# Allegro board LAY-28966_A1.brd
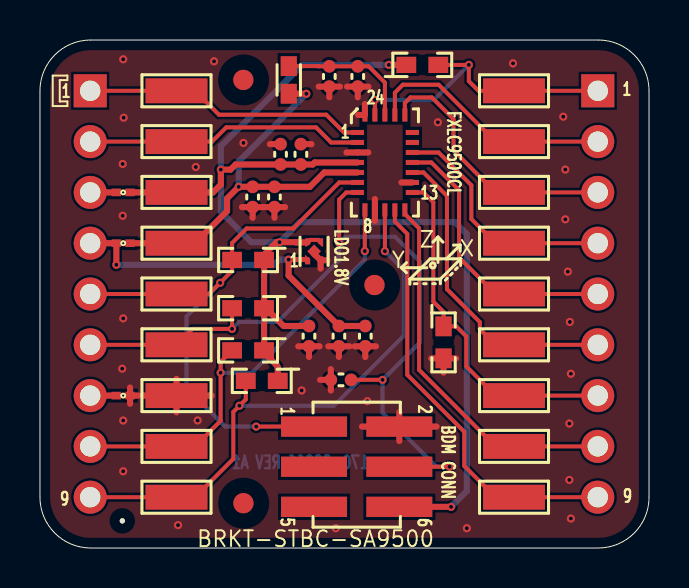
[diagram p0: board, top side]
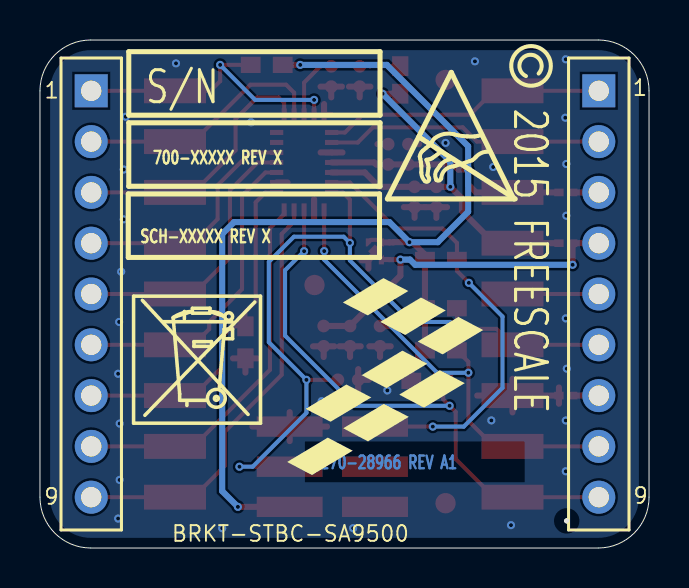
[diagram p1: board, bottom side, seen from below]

Outline 30.48 x 25.4 mm; copper layers: TOP, BOTTOM. Coordinates in mm from the lower left corner of the outline.
Outline path: 0,22.86 0,2.54 arc(0.74,0.74) 2.54,0 27.94,0 arc(29.74,0.74) 30.48,2.54 30.48,22.86 arc(29.74,24.66) 27.94,25.4 2.54,25.4 arc(0.74,24.66) 0,22.86

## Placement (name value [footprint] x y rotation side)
BKG1  0805  [TESTPOINT_122X049MIL]  6.83 12.7 0 top
C1  1uF  [CC0402_25]  10.64 17.55 270 top
C2  0.1uF  [CC0402_25]  11.73 17.55 270 top
C3  1uF  [CC0402_25]  14.48 23.58 270 top
C4  0.1uF  [CC0402_25]  15.9 23.58 270 top
C5  1uF  [CC0402_25]  12.04 19.68 90 top
C6  0.1uF  [CC0402_25]  13.06 19.68 90 top
C7  0.1uF  [CC0402_25]  13.46 10.59 270 top
C8  1uF  [CC0402_25]  16.28 10.59 270 top
C9  0.1uF  [CC0402_25]  14.96 10.59 270 top
C10  22pF  [CC0402_25]  15.06 8.41 180 top
GND1  0805  [TESTPOINT_122X049MIL]  6.83 7.62 0 top
INT0  0805  [TESTPOINT_122X049MIL]  23.72 10.16 0 top
INT1  0805  [TESTPOINT_122X049MIL]  23.72 7.62 0 top
IO6  0805  [TESTPOINT_122X049MIL]  23.72 12.7 0 top
IO7  0805  [TESTPOINT_122X049MIL]  23.72 15.24 0 top
IO12  0805  [TESTPOINT_122X049MIL]  23.72 17.78 0 top
IO13  0805  [TESTPOINT_122X049MIL]  23.72 20.32 0 top
J1  TSW-109-08-G-S  [HDR9_2P54_3X23]  2.51 22.86 180 bottom
J2  TSW-109-08-G-S  [HDR9_2P54_3X23]  27.91 22.86 180 bottom
J3  HDR_2X3  [HDR203_TMM_SM]  15.85 4.06 0 top
L1  600OHM  [IND_0603]  12.45 23.4 270 top
MCL1  0805  [TESTPOINT_122X049MIL]  6.83 22.86 0 top
MDA1  0805  [TESTPOINT_122X049MIL]  6.83 20.32 0 top
NOREF  -  []  5.71 1.92 90 top
NOREF#2  -  []  14.17 14.17 90 top
NOREF#3  -  []  22.72 12.08 90 top
NOREF#4  -  []  22.72 3.17 0 top
NOREF#5  -  []  13.54 18.87 0 top
NOREF#6  -  []  7.83 9.53 90 top
NOREF#7  -  []  5.71 17.16 90 top
NOREF#8  -  []  22.72 9.53 0 top
NOREF#9  -  []  7.83 14.61 90 top
NOREF#10  -  []  5.71 7 90 top
NOREF#11  -  []  22.72 14.62 90 top
NOREF#12  -  []  5.83 4.45 0 top
NOREF#13  -  []  5.83 9.53 0 top
NOREF#14  -  []  22.72 1.92 90 top
NOREF#15  -  []  16.31 19.37 90 top
NOREF#16  -  []  5.71 23.49 0 top
NOREF#17  -  []  4.88 0 90 top
NOREF#18  -  []  22.72 5.71 0 top
NOREF#19  -  []  22.72 7 90 top
NOREF#20  -  []  22.72 1.91 0 top
NOREF#21  -  []  5.71 3.17 0 top
NOREF#22  -  []  24.72 19.69 90 top
NOREF#23  -  []  27.08 0 90 top
NOREF#24  -  []  22.72 9.54 90 top
NOREF#25  -  []  24.72 14.61 90 top
NOREF#26  -  []  5.83 19.69 0 top
NOREF#27  -  []  24.72 12.07 90 top
NOREF#28  -  []  5.71 18.41 0 top
NOREF#29  -  []  16.31 19.37 90 top
NOREF#30  -  []  5.71 13.33 0 top
NOREF#31  -  []  22.72 12.07 0 top
NOREF#32  -  []  22.72 23.49 0 top
NOREF#33  -  []  -12.95 -49.48 0 top
NOREF#34  -  [unnamed#2]  10.18 2.24 180 top
NOREF#35  -  []  7.83 6.99 90 top
NOREF#36  -  []  22.72 4.46 90 top
NOREF#37  -  []  5.83 22.23 0 top
NOREF#38  -  []  22.72 18.41 0 top
NOREF#39  -  []  5.71 9.54 90 top
NOREF#40  -  [unnamed#2]  10.18 23.4 180 top
NOREF#41  -  []  22.72 8.25 0 top
NOREF#42  -  []  5.71 8.25 0 top
NOREF#43  -  []  4.19 1.32 0 top
NOREF#44  -  []  5.71 20.95 0 top
NOREF#45  -  []  5.83 6.99 0 top
NOREF#46  -  []  7.83 22.23 90 top
NOREF#47  -  []  22.72 4.45 0 top
NOREF#48  -  []  22.72 19.7 90 top
NOREF#49  -  []  -310.77 -262.2 0 top
NOREF#50  -  []  22.72 6.99 0 top
NOREF#51  -  []  22.72 19.69 0 top
NOREF#52  -  []  5.71 12.08 90 top
NOREF#53  -  []  22.72 14.61 0 top
NOREF#54  -  []  24.72 9.53 90 top
NOREF#55  -  []  22.72 10.79 0 top
NOREF#56  -  []  7.83 19.69 90 top
NOREF#57  -  []  297.56 -38.68 0 top
NOREF#58  -  []  0 22.65 0 top
NOREF#59  -  []  5.71 22.24 90 top
NOREF#60  -  [unnamed#2]  4.12 1.36 180 top
NOREF#61  -  []  15.54 19.1 90 top
NOREF#62  -  []  22.72 13.33 0 top
NOREF#63  -  []  5.71 5.71 0 top
NOREF#64  -  []  7.83 12.07 90 top
NOREF#65  -  []  5.83 1.91 0 top
NOREF#66  -  []  5.71 4.46 90 top
NOREF#67  -  []  16.31 19.37 90 top
NOREF#68  -  []  22.72 15.87 0 top
NOREF#69  -  [unnamed#2]  16.74 13.15 180 top
NOREF#70  -  []  13.76 19.37 0 top
NOREF#71  -  []  14.54 19.1 0 top
NOREF#72  -  []  7.83 17.15 90 top
NOREF#73  -  []  24.72 17.15 90 top
NOREF#74  -  []  -284.73 262.94 0 top
NOREF#75  -  []  22.72 22.24 90 top
NOREF#76  -  []  25.15 2.97 0 top
NOREF#77  -  []  5.71 19.7 90 top
NOREF#78  -  []  7.83 1.91 90 top
NOREF#79  -  []  7.83 4.45 90 top
NOREF#80  -  []  16.54 18.87 90 top
NOREF#81  -  []  5.83 14.61 0 top
NOREF#82  -  []  0 4.18 0 top
NOREF#83  -  []  22.72 22.23 0 top
NOREF#84  -  []  5.71 14.62 90 top
NOREF#85  -  []  22.72 17.16 90 top
NOREF#86  -  []  29.81 24.58 0 top
NOREF#87  -  []  13.39 14.42 0 top
NOREF#88  -  []  14.24 14.31 90 top
NOREF#89  -  []  5.83 12.07 0 top
NOREF#90  -  []  5.71 10.79 0 top
NOREF#91  -  []  24.72 6.99 90 top
NOREF#92  -  []  24.72 1.91 90 top
NOREF#93  -  []  14.54 19.1 90 top
NOREF#94  -  []  5.83 17.15 0 top
NOREF#95  -  []  5.71 15.87 0 top
NOREF#96  -  []  13.19 14.31 0 top
NOREF#97  -  []  16.52 21.87 0 top
NOREF#98  -  []  22.72 20.95 0 top
NOREF#99  -  []  22.72 17.15 0 top
NOREF#100  -  []  24.72 4.45 90 top
NOREF#101  -  []  24.72 22.23 90 top
NOREF#102  -  []  25.79 6.24 180 bottom
NOREF#103  -  []  26.06 14.53 180 bottom
NOREF#104  -  []  26.29 2.46 180 bottom
NOREF#105  -  []  5.78 23.98 270 bottom
NOREF#106  -  []  26.04 18.08 180 bottom
NOREF#107  -  []  18.11 3.65 180 bottom
NOREF#108  -  []  26.04 21.64 180 bottom
NOREF#109  -  []  4.43 24.57 180 bottom
P1V8  0805  [TESTPOINT_122X049MIL]  6.83 15.24 0 top
P3V3  0805  [TESTPOINT_122X049MIL]  6.83 17.78 0 top
PDB1  0805  [TESTPOINT_122X049MIL]  23.72 22.86 0 top
R1  4.7K  [RC0603]  10.41 9.88 180 top
R2  4.7K  [RC0603]  11.1 8.36 180 top
R3  4.7K  [RC0603]  10.41 11.99 180 top
R4  10K  [RC0603]  19.13 24.16 0 top
R5  1K  [RC0603]  10.41 14.4 180 top
R6  4.7K  [RC0603]  20.2 10.28 270 top
RST1  0805  [TESTPOINT_122X049MIL]  6.83 10.16 0 top
SCL1  0805  [TESTPOINT_122X049MIL]  6.83 5.08 0 top
SDA1  0805  [TESTPOINT_122X049MIL]  6.83 2.54 0 top
SDO1  0805  [TESTPOINT_122X049MIL]  23.72 2.54 0 top
SH1  0  [SH0201]  4.17 17.78 0 top
SH2  0  [SH0201]  4.17 15.24 0 top
SH3  0  [SH0201]  4.17 7.62 0 top
SSB1  0805  [TESTPOINT_122X049MIL]  23.72 5.08 0 top
U1  FXLC95000CL  [LGA24_0P5_3X5]  17.26 19.28 0 top
U2  MIC5317-1.8YMT  [TDFN5_1P05X1P05MM]  13.72 14.83 0 top

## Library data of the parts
BKG1 GND1 INT0 INT1 IO6 IO7 IO12 IO13 MCL1 MDA1 P1V8 P3V3 PDB1 RST1 SCL1 SDA1 SDO1 SSB1 = TEST_POINT
C1-C9 = CAP_NP: tolerance: 10%
C10 = CAP_NP
J1 J2 = CON_HDR_1X9
J3 = CONN_HDR_3X2
L1 = INDUCTOR
R1-R6 = RES
SH1-SH3 = RES_SHORT-2: Tolerance: TOLERANCE; User Part Number: 470-76473
U1 = MXLC9560C_24P
U2 = MIC5317_TDFN5P

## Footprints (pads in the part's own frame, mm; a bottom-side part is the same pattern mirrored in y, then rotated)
CC0402_25
  round 0.635 smd: 1(-0.508,0) 2(0.508,0)
HDR9_2P54_3X23
  rect 1.651x1.651 hole 1.016: 1(0,0)
  round 1.651 hole 1.016: 2(0,-2.54) 3(0,-5.08) 4(0,-7.62) 5(0,-10.16) 6(0,-12.7) 7(0,-15.24) 8(0,-17.78) 9(0,-20.32)
HDR203_TMM_SM
  rect 3.302x1.016 smd: 1(-2.134,2.007) 2(2.134,2.007) 3(-2.134,0) 4(2.134,0) 5(-2.134,-2.007) 6(2.134,-2.007)
IND_0603
  rect 0.991x0.813 smd: 1(-0.69,0) 2(0.69,0)
LGA24_0P5_3X5
  rect 0.66x0.254 smd: 1(-1.375,1.5) 2(-1.375,1) 3(-1.375,0.5) 4(-1.375,0) 5(-1.375,-0.5) 6(-1.375,-1) 7(-1.375,-1.5) 13(1.375,-1.5) 14(1.375,-1) 15(1.375,-0.5) 16(1.375,0) 17(1.375,0.5) 18(1.375,1) 19(1.375,1.5)
  rect 0.254x0.66 smd: 8(-1,-2.375) 9(-0.5,-2.375) 10(0,-2.375) 11(0.5,-2.375) 12(1,-2.375) 20(1,2.375) 21(0.5,2.375) 22(0,2.375) 23(-0.5,2.375) 24(-1,2.375)
RC0603
  rect 0.991x0.813 smd: 1(-0.8,0) 2(0.8,0)
SH0201
  rect 0.47x0.381 smd: 1(-0.343,0) 2(0.343,0)
TDFN5_1P05X1P05MM
  custom 0.064x0.064 smd: 1(-0.325,-0.409) 2(0.325,-0.447) 3(0.325,0.447) 4(-0.325,0.447)
  rect 0.483x0.483 smd rot 45: 5(0,0)
TESTPOINT_122X049MIL
  rect 3.099x1.245 smd: 1(0,0)
unnamed#2
  round 1.016 smd: (0,0)

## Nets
GND: C1.2 C2.2 C3.2 C4.2 C5.2 C6.2 C7.2 C8.2 C9.2 C10.2 GND1.1 J3.2(B1) R6.2 SH3.2 U1.3(VSSIO) U1.9(VSS_9) U1.14(VSS_14) U1.24(VSSA) U2.2(GND) U2.5(EPAD)
P1V8: C1.1 C2.1 L1.2 P1V8.1 SH2.2 U1.5(VDD)
P1V8_V: C8.1 C9.1 J1.4 SH2.1 U2.1(VOUT)
P3V3: C5.1 C6.1 C7.1 J3.6(B3) P3V3.1 R1.1 R2.1 R3.1 R4.1 R5.1 SH1.2 U1.4(VDDIO) U2.3(EN) U2.4(VIN)
BKGD: BKG1.1 J1.5 J3.1(A1) R5.2 U1.6(BKGD/MS/RGPIO9)
GPIO6: IO6.1 J2.5 U1.16(RGPIO6/AN0-/TPMCH0)
GPIO7: IO7.1 J2.4 U1.17(RGPIO7/AN1+/TPMCH1)
GPIO12: IO12.1 J2.3 U1.20(MISO1/RGPIO12)
GPIO13: IO13.1 J2.2 U1.21(S\S\1\/RGPIO13)
INT_I: INT1.1 J2.7 R6.1 U1.13(RGPIO4/INT_I)
INT_O: INT0.1 J2.6 U1.15(RGPIO5/PDB_A/INT_O)
M_I2C_SCL: J1.1 MCL1.1 U1.1(SCL1/RGPIO14)
M_I2C_SDA: J1.2 MDA1.1 U1.2(SDA1/RGPIO15)
PDB_B: J2.1 PDB1.1 R4.2 U1.23(RGPIO8/PDB_B)
RESETB: C10.1 J1.6 J3.4(B2) R3.2 RST1.1 U1.7(R\E\S\E\T\)
S_I2C_SCL_SCLK: J1.8 R1.2 SCL1.1 U1.8(SCL0/RGPIO0/SCLK)
S_I2C_SDA_MOSI: J1.9 R2.2 SDA1.1 U1.10(SDA0/RGPIO1/MOSI)
S_SPI_SDO: J2.9 SDO1.1 U1.11(RGPIO2/SCL1/MISO)
S_SSB_GPIO3: J2.8 SSB1.1 U1.12(RGPIO3/SDA1/S\S\)
N20846695: C3.1 C4.1 L1.1 U1.22(VDDA)
N20846720: J1.3 SH1.1
N20846848: J1.7 SH3.1

Pads without a net: J3 3 5; U1 18 19

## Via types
v1: diameter 0.406, hole 0.203, TOP to BOTTOM, 48 vias

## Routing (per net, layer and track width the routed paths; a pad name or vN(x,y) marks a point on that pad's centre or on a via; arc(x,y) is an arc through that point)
GND: length 32.5
  TOP w0.305: 11.2,17.04 C2.2 ; C2.2 12.27,17.04 ; C2.2 11.73,16.51 ; SH3.2 4.51,8.03 ; SH3.2 4.96,7.62 ; SH3.2 4.51,7.21 ; 19.58,9.48 R6.2 ; R6.2 20.2,8.77 ; R6.2 20.82,9.48 ; U2.5 13.72,14.71 U2.2 ; 11.51,20.19 C5.2 ; 15.37,23.07 C4.2 ; C4.2 15.9,22.53 ; C4.2 16.44,23.07 ; 14.55,7.87 C10.2 ; C10.2 14.55,8.94 ; C10.2 14.02,8.41 ; 14.48,22.53 C3.2 ; C3.2 13.95,23.07 ; C3.2 15.01,23.07 ; GND1.1 6.83,8.46 ; GND1.1 8.6,7.62 ; GND1.1 6.83,6.78 ; GND1.1 5.07,7.62 ; 10.64,16.51 C1.2 ; C1.2 11.18,17.04 ; C1.2 10.11,17.04 ; C8.2 16.82,10.08 ; C8.2 16.28,9.55 ; C8.2 15.75,10.08 ; 18.09,18.28 U1.14 ; 16.76,17.45 U1.9 16.76,16.35 ; U2.2 14.39,14.39 ; U2.2 14.04,13.97 ; C9.2 15.49,10.08 ; C9.2 14.96,9.55 ; C9.2 14.43,10.08 ; 12.93,10.08 C7.2 ; C7.2 14,10.08 ; C7.2 13.46,9.55 ; 17.98,5.35 J3.2 ; J3.2 17.98,6.8 ; J3.2 16.12,6.07 ; J3.2 19.85,6.07 ; 15.34,19.78 U1.3 16.43,19.78 ; C6.2 13.59,20.19 ; 16.26,22.2 U1.24 15.92,21.65
  vias: v1(4.17,24.43) v1(4.14,19.2) v1(4.14,16.61) v1(4.17,11.48) v1(4.11,8.97) v1(4.17,6.38) v1(4.17,3.84) v1(4.19,21.51) v1(6.91,1.14) v1(7.8,19.05) v1(7.89,6.38) v1(8.71,24.33) v1(10.18,20.25) v1(13.1,7.88) v1(14.81,0.99) v1(16.38,7.34) v1(19.91,21.29) v1(21.36,0.99) v1(23.67,24.23) v1(26.19,21.56) v1(26.29,18.92) v1(26.29,16.43) v1(26.42,13.82) v1(26.52,11.3) v1(26.57,8.71) v1(26.49,6.22) v1(26.49,3.4) v1(26.57,1.47)
P1V8: length 20.2
  TOP w0.305: U1.5 14.22,18.78 13.51,18.06 C2.1 C1.1 v1(9.94,18.06) 9.36,17.48 9.36,16.84 7.76,15.24 P1V8.1 SH2.2 ; L1.2 12.84,22.71 12.84,22.71 v1(13.33,22.71)
  BOTTOM w0.305: v1(13.33,22.71) 9.94,19.32 v1(9.94,18.06)
P1V8_V: length 17.8
  TOP w0.254: v1(12.44,14.42) 13.01,14.42 13.01,14.42 U2.1
  TOP w0.305: J1.4 SH2.1 v1(3.82,14.16) ; v1(12.44,14.42) 12.44,13.62 C9.1 C8.1
  BOTTOM w0.305: v1(12.44,14.42) 11.96,14.42 11.7,14.16 v1(3.82,14.16)
P3V3: length 69.2
  TOP w0.203: U2.3 13.92,15.4 13.52,15.4 U2.4
  TOP w0.305: U1.4 13.75,19.28 13.65,19.18 C6.1 C5.1 9.79,19.18 9.54,18.92 v1(9.05,18.92) 9.05,18.17 8.66,17.78 P3V3.1 SH1.2 ; R2.1 11.9,9.04 11.86,9.08 11.86,9.12 11.21,9.77 R1.1 R3.1 ; J3.6 v1(20.57,2.06) ; R4.1 v1(17.46,24.16) ; R3.1 R5.1 11.21,14.67 11.84,15.29 v1(11.99,15.29) 12.8,15.29 12.81,15.28 12.99,15.28 12.99,15.28 U2.4 ; R3.1 11.3,11.99 12.19,11.1 C7.1
  BOTTOM w0.305: v1(17.46,24.16) 13.12,24.16 9.05,20.09 v1(9.05,18.92) 9.05,16.81 10.57,15.29 v1(11.99,15.29) 12.99,16.29 20.76,16.29 21.36,15.7 21.36,2.84 v1(20.57,2.06)
BKGD: length 29.6
  TOP w0.203: v1(10.82,6.07) J3.1 ; U1.6 14.97,18.28 12.67,15.98 10.34,15.98 9.61,15.25 R5.2 9.61,13.86 v1(9.02,13.26) 8.46,12.7 BKG1.1 J1.5
  BOTTOM w0.203: v1(9.02,13.26) 7.33,11.57 7.33,8.01 9.27,6.07 v1(10.82,6.07)
GPIO6: length 14
  TOP w0.203: J2.5 IO6.1 22.8,12.7 20.97,14.52 20.97,17.89 19.59,19.28 U1.16
GPIO7: length 12.1
  TOP w0.203: U1.17 19.95,19.78 21.59,18.14 21.59,16.45 22.8,15.24 IO7.1 J2.4
GPIO12: length 13.3
  TOP w0.203: U1.20 18.26,22.25 18.54,22.53 19.61,22.53 20.69,21.45 20.69,19.88 22.8,17.78 IO12.1 J2.3
GPIO13: length 12.6
  TOP w0.203: U1.21 17.76,22.77 18.16,23.16 19.95,23.16 22.8,20.32 IO13.1 J2.2
INT_I: length 17.7
  TOP w0.203: U1.13 19.2,17.78 19.69,17.29 19.69,12.32 20.2,11.81 R6.1 20.83,11.08 21.34,10.58 21.34,9.08 22.8,7.62 INT1.1 J2.7
INT_O: length 15.8
  TOP w0.203: U1.15 19.2,18.78 20.37,17.6 20.37,12.94 22.01,11.3 22.01,10.94 22.8,10.16 INT0.1 J2.6
M_I2C_SCL: length 14.2
  TOP w0.203: U1.1 15.22,20.78 14.33,21.66 8.96,21.66 7.76,22.86 MCL1.1 J1.1
M_I2C_SDA: length 14
  TOP w0.203: U1.2 14.57,20.28 13.82,21.03 9.32,21.03 8.61,20.32 MDA1.1 J1.2
PDB_B: length 15.2
  TOP w0.203: J2.1 PDB1.1 21.95,22.86 21.46,23.34 v1(21.46,24.16) R4.2 ; U1.23 v1(16.76,22.41)
  BOTTOM w0.203: v1(21.46,24.16) 19.71,22.41 v1(16.76,22.41)
RESETB: length 40.9
  TOP w0.203: C10.1 v1(17.14,8.41) ; R3.2 v1(9.61,10.96) 7.63,10.96 RST1.1 J1.6 ; U1.7 15.33,17.78 14.97,17.42 v1(14.97,15.26) ; J3.4 v1(20.5,4.06)
  BOTTOM w0.203: v1(9.61,10.96) 9.96,11.3 11.89,11.3 14.97,14.38 v1(14.97,15.26) 15.28,15.57 17.77,15.57 19.03,14.31 19.03,10.29 v1(17.14,8.41) 17.14,6.76 19.84,4.06 v1(20.5,4.06)
S_I2C_SCL_SCLK: length 22.9
  TOP w0.203: v1(16.26,14.85) 16.26,15.95 16.26,15.96 U1.8 ; R1.2 9.04,9.31 v1(9.04,8.76) 9.04,6.36 7.76,5.08 SCL1.1 J1.8
  BOTTOM w0.203: v1(16.26,14.85) 16.26,14.41 10.6,8.76 v1(9.04,8.76)
S_I2C_SDA_MOSI: length 28.5
  TOP w0.203: J1.9 SDA1.1 7.76,2.54 9.68,4.46 9.68,6.81 v1(9.98,7.11) 10.3,7.43 R2.2 ; v1(17.26,14.84) U1.10
  BOTTOM w0.203: v1(17.26,14.84) 18.21,13.89 18.21,10.62 14.71,7.11 v1(9.98,7.11)
S_SPI_SDO: length 21.6
  TOP w0.203: U1.11 17.76,16.32 18.38,15.7 18.38,8.66 21.23,5.81 21.23,4.1 22.8,2.54 SDO1.1 J2.9
S_SSB_GPIO3: length 18.8
  TOP w0.203: J2.8 SSB1.1 22.8,5.08 18.97,8.91 18.97,15.99 18.26,16.7 U1.12
N20846695: length 6.8
  TOP w0.203: L1.1 13.93,24.09 13.93,24.08 C3.1 C4.1 16.45,24.08 17.26,23.27 U1.22
N20846720: length 1.3
  TOP w0.305: J1.3 SH1.1
N20846848: length 1.3
  TOP w0.305: J1.7 SH3.1

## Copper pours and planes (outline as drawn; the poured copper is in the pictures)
GND on TOP, BOTTOM: 29.97,2.54 29.38,1.1 27.94,0.51 2.54,0.51 1.1,1.1 0.51,2.54 0.51,22.86 1.1,24.3 2.54,24.89 27.94,24.89 29.38,24.3 29.97,22.86

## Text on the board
BOTTOM: 170-28966 REV A1 | 5 OF 8 | L2_SS
Board Geometry/Soldermask Bottom: 6 OF 8 | SECONDARY SOLDERMASK
Ref Des/Silkscreen Bottom: BRKT-STBC-SA9500 | 7 OF 8 | SECONDARY SILKSCREEN
User.Comments: 17 | 1 OF 1 | TEST PROBE | 1/1 | 1
TOP: 4 OF 8 | L1_PS
Board Geometry/Soldermask Top: 3 OF 8 | PRIMARY SOLDERMASK
Ref Des/Silkscreen Top: LDO1.8V | BDM CONN | FXLC9500CL | BRKT-STBC-SA9500 | Y | Z | X | 2 OF 8 | PRIMARY SILKSCREEN
DIMENSION: (X4) | PRIMARY DATUM | GRID ORIGIN | 0.062" THICK +/-10%
BODY_CENTER: 22. INTENTIONAL SHORTS AT: | SH1  N20846720 & P3V3 | SH2  P1V8_V & P1V8 | SH3  N20846848 & GND | 16 | 17 | 8
PASTEMASK_TOP: 1 OF 8 | PASTEMASK TOP
User.5: 8 OF 8 | SECONDARY PASTEMASK
User.12: 170-28966 | LAY-28966 | FAB-28966 | 10-11-15 | A1 | DFA AND DFM UPDATES TO LAYOUT
User.16: FIGURE | SIZE | 8.0 | 40.0 | 25.0 | DRILL CHART: TOP to BOTTOM | ALL UNITS ARE IN MILS | TOLERANCE | +0.0/-8.0 | +3.0/-3.0 | +2.0/-2.0 | PLATED | NON-PLATED | QTY | 48 | 18 | 1
